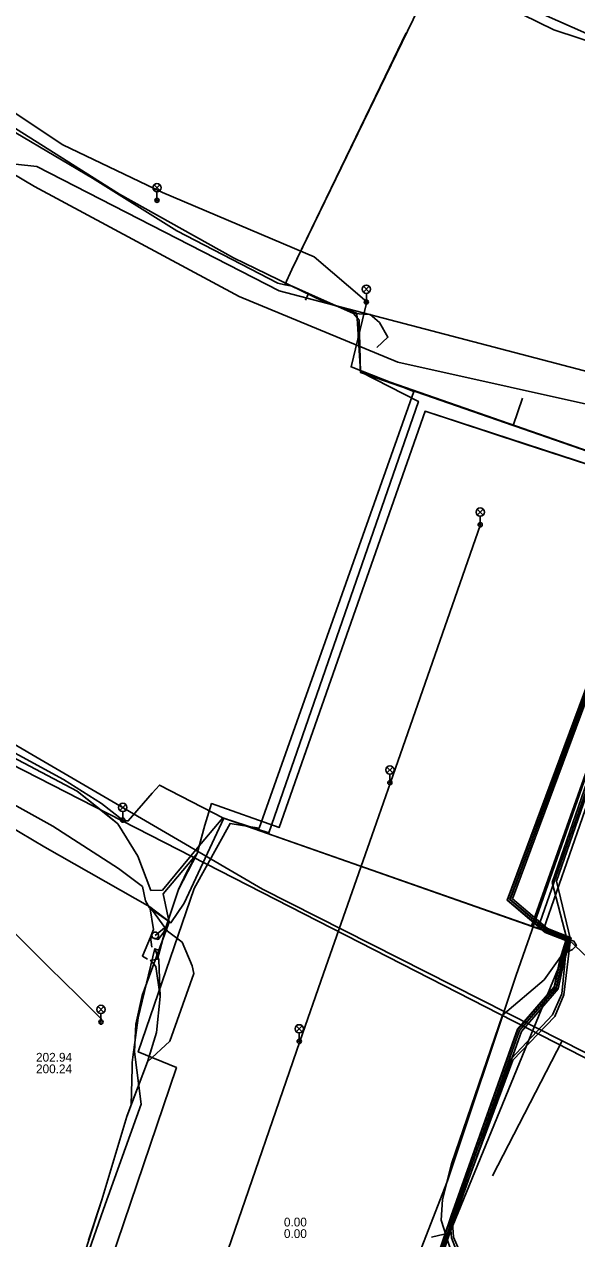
# Model space of a CAD drawing. Extents: x -598932 to -598196, y -1162210 to -1161504.
# Drawn here: x -598603 to -598552.8, y -1162086.4 to -1161976.1 of the extents above; entities that cross this region are included whole.
import ezdxf

# ---------------------------------------------------------------- set-up
doc = ezdxf.new("R2010")
doc.units = 0
for name, color, linetype in [('Vrstva 1', 7, 'Continuous'), ('Vrstva 12', 7, 'Continuous'), ('Vrstva 14', 7, 'Continuous'), ('Vrstva 19', 7, 'Continuous'), ('Vrstva 33', 7, 'Continuous'), ('Vrstva 4', 7, 'Continuous'), ('Vrstva 42', 7, 'Continuous'), ('Vrstva 44', 7, 'Continuous'), ('Vrstva 53', 7, 'Continuous'), ('Vrstva 55', 7, 'Continuous'), ('Vrstva 58', 7, 'Continuous'), ('Vrstva 9', 7, 'Continuous')]:
    doc.layers.add(name, color=color, linetype=linetype)

msp = doc.modelspace()

# ---------------------------------------------------------------- linework, layer by layer
at = {"layer": 'Vrstva 1'}
msp.add_line((-598560.414, -1162080.726), (-598554.112, -1162068.468), dxfattribs=at)
at = {"layer": 'Vrstva 12'}
msp.add_line((-598554.87, -1161976.6), (-598544.19, -1161980.1), dxfattribs=at)
for points in [[(-598627.45, -1161930.97), (-598602.02, -1161951.17), (-598577.74, -1161965.37), (-598554.87, -1161976.6)], [(-598553.63, -1162059.2), (-598555.8, -1162058.35), (-598542.8, -1162021.02), (-598541.73, -1162018.85), (-598539.21, -1162019.28)], [(-598553.63, -1162059.2), (-598553.03, -1162059.41), (-598552.81, -1162059.79), (-598553.17, -1162060.16), (-598554.06, -1162060.58), (-598555.74, -1162062.92), (-598559.51, -1162066.12), (-598564.16, -1162079.63), (-598564.97, -1162082.87), (-598565.09, -1162084.75), (-598563.96, -1162088.26)]]:
    msp.add_lwpolyline(points, dxfattribs=at)
at = {"layer": 'Vrstva 14'}
for points in [[(-598553.423, -1162069.27), (-598647.472, -1162021.146), (-598651.917, -1162018.863), (-598713.299, -1161971.957), (-598714.211, -1161971.254)], [(-598217.743, -1162202.648), (-598218.334, -1162201.688), (-598338.63, -1162114.69), (-598384.62, -1162107.99), (-598422.17, -1162096.1), (-598509.221, -1162075.902), (-598509.921, -1162075.996), (-598510.741, -1162076.086), (-598530.41, -1162081.101), (-598553.423, -1162069.27)]]:
    msp.add_lwpolyline(points, dxfattribs=at)
at = {"layer": 'Vrstva 19'}
msp.add_lwpolyline([(-598526.7, -1162021.32), (-598533.53, -1162012.45), (-598534.5, -1162012.19), (-598579.8, -1162000.3), (-598601.83, -1161989.02), (-598609.34, -1161988.18)], dxfattribs=at)
at = {"layer": 'Vrstva 33'}
for p, q in [((-598591.175, -1161990.675), (-598590.645, -1161991.205)), ((-598591.175, -1161991.205), (-598590.645, -1161990.675)), ((-598590.91, -1161992.09), (-598590.91, -1161991.315)), ((-598572.152, -1161999.9), (-598571.622, -1162000.43)), ((-598572.152, -1162000.43), (-598571.622, -1161999.9)), ((-598571.887, -1162001.315), (-598571.887, -1162000.54)), ((-598561.809, -1162020.152), (-598561.279, -1162020.682)), ((-598561.809, -1162020.682), (-598561.279, -1162020.152)), ((-598561.544, -1162021.567), (-598561.544, -1162020.792)), ((-598570.014, -1162043.577), (-598569.484, -1162044.107)), ((-598570.014, -1162044.107), (-598569.484, -1162043.577)), ((-598569.749, -1162044.992), (-598569.749, -1162044.217)), ((-598594.283, -1162046.988), (-598593.753, -1162047.518)), ((-598594.283, -1162047.518), (-598593.753, -1162046.988)), ((-598594.018, -1162048.403), (-598594.018, -1162047.628)), ((-598596.268, -1162065.34), (-598595.738, -1162065.87)), ((-598596.268, -1162065.87), (-598595.738, -1162065.34)), ((-598596.003, -1162066.755), (-598596.003, -1162065.98)), ((-598578.251, -1162067.1), (-598577.721, -1162067.63)), ((-598578.251, -1162067.63), (-598577.721, -1162067.1)), ((-598577.986, -1162068.515), (-598577.986, -1162067.74))]:
    msp.add_line(p, q, dxfattribs=at)
for centre, radius in [((-598590.91, -1161990.94), 0.375), ((-598590.91, -1161992.09), 0.19), ((-598590.91, -1161992.09), 0.05), ((-598571.887, -1162000.165), 0.375), ((-598571.887, -1162001.315), 0.19), ((-598571.887, -1162001.315), 0.05), ((-598561.544, -1162020.417), 0.375), ((-598561.544, -1162021.567), 0.19), ((-598561.544, -1162021.567), 0.05), ((-598569.749, -1162043.842), 0.375), ((-598569.749, -1162044.992), 0.19), ((-598569.749, -1162044.992), 0.05), ((-598594.018, -1162047.253), 0.375), ((-598594.018, -1162048.403), 0.19), ((-598594.018, -1162048.403), 0.05), ((-598596.003, -1162065.605), 0.375), ((-598596.003, -1162066.755), 0.19), ((-598596.003, -1162066.755), 0.05), ((-598577.986, -1162067.365), 0.375), ((-598577.986, -1162068.515), 0.19), ((-598577.986, -1162068.515), 0.05)]:
    msp.add_circle(centre, radius, dxfattribs=at)
at = {"layer": 'Vrstva 42'}
for p, q in [((-598564.33, -1161968.826), (-598578.662, -1161998.381)), ((-598578.662, -1161998.381), (-598579.286, -1161999.751)), ((-598577.155, -1162000.549), (-598577.42, -1162001.147)), ((-598577.155, -1162000.549), (-598577.42, -1162001.147)), ((-598575.77, -1162001.27), (-598577.155, -1162000.549)), ((-598572.43, -1162007.67), (-598539.14, -1162019.27)), ((-598572.43, -1162007.73), (-598539.14, -1162019.27)), ((-598558.556, -1162012.539), (-598557.7, -1162010.07)), ((-598558.556, -1162012.539), (-598557.7, -1162010.07)), ((-598543.52, -1162020.32), (-598558.28, -1162062.5)), ((-598579.821, -1162049.085), (-598577.366, -1162042.079)), ((-598586.555, -1162048.852), (-598585.946, -1162046.908)), ((-598586.555, -1162048.852), (-598587.25, -1162051.43)), ((-598584.94, -1162048.187), (-598553.644, -1162059.173)), ((-598591.5, -1162059.05), (-598591.39, -1162059.955)), ((-598591.5, -1162059.05), (-598591.39, -1162059.955)), ((-598591.5, -1162059.05), (-598591.39, -1162059.955)), ((-598591.07, -1162058.88), (-598590.08, -1162058.08)), ((-598558.28, -1162062.5), (-598564.52, -1162081.19)), ((-598564.52, -1162081.19), (-598572.6, -1162101.87))]:
    msp.add_line(p, q, dxfattribs=at)
for points in [[(-598696.43, -1161910.03), (-598694.81, -1161909.35), (-598691.6, -1161908.88), (-598690.47, -1161909.23), (-598684.69, -1161915.57), (-598676.56, -1161921.46), (-598666.44, -1161931.11), (-598661.49, -1161936.08), (-598655.62, -1161944.08), (-598644.64, -1161954.28), (-598635.19, -1161962.23), (-598623.88, -1161971.66), (-598615.13, -1161977.53), (-598604.9, -1161984.84), (-598594.32, -1161991.54), (-598583.95, -1161997.32), (-598575.77, -1162001.27), (-598572.76, -1162002.34), (-598572.68, -1162003.32), (-598572.43, -1162007.67)], [(-598616.75, -1161975.23), (-598616.89, -1161975.85), (-598616.35, -1161976.76), (-598613.51, -1161979.33), (-598607.26, -1161983.88), (-598596.76, -1161990.06), (-598589.11, -1161994.85), (-598579.94, -1161999.61), (-598579.286, -1161999.751)], [(-598578.662, -1161998.381), (-598570.182, -1161980.834), (-598568.28, -1161976.86)], [(-598584.94, -1162048.187), (-598587.373, -1162051.113), (-598590.418, -1162054.759), (-598591.461, -1162054.798), (-598592.644, -1162051.677), (-598594.475, -1162048.726), (-598595.514, -1162047.861), (-598598.175, -1162045.777), (-598603.555, -1162042.914), (-598615.772, -1162036.634), (-598619.898, -1162034.24), (-598623.918, -1162031.949), (-598625.034, -1162030.4), (-598630.842, -1162026.844), (-598645.114, -1162018.576), (-598650.929, -1162014.808), (-598655.57, -1162011.409), (-598660.099, -1162008.595), (-598670.573, -1162001.081), (-598684.323, -1161990.333), (-598691.62, -1161985.078), (-598695, -1161981.986), (-598698.099, -1161980.56)], [(-598577.42, -1162001.147), (-598577.155, -1162000.549), (-598578.64, -1161999.89), (-598579.286, -1161999.751), (-598578.662, -1161998.381)], [(-598577.155, -1162000.549), (-598578.64, -1161999.89), (-598579.286, -1161999.751)], [(-598573.05, -1162002.37), (-598577.155, -1162000.549), (-598577.42, -1162001.147)], [(-598577.155, -1162000.549), (-598573.05, -1162002.37), (-598572.53, -1162002.96), (-598572.43, -1162007.73), (-598539.14, -1162019.27)], [(-598558.556, -1162012.539), (-598572.43, -1162007.73), (-598572.53, -1162002.96), (-598573.05, -1162002.37), (-598577.155, -1162000.549)], [(-598575.77, -1162001.27), (-598572.76, -1162002.34), (-598572.68, -1162003.32), (-598572.43, -1162007.67)], [(-598573.05, -1162002.37), (-598571.55, -1162002.45), (-598570.7, -1162003.2), (-598569.93, -1162004.52), (-598570.95, -1162005.46)], [(-598573.05, -1162002.37), (-598572.53, -1162002.96), (-598572.43, -1162007.73)], [(-598584.87, -1162048.23), (-598580.734, -1162049.565), (-598567.159, -1162010.365), (-598572.43, -1162007.67)], [(-598536.03, -1162015.6), (-598537.275, -1162019.398), (-598537.651, -1162020.546), (-598543.652, -1162018.729), (-598566.56, -1162011.25), (-598579.821, -1162049.085), (-598585.946, -1162046.908), (-598586.555, -1162048.852), (-598587.25, -1162051.43)], [(-598585.946, -1162046.908), (-598579.821, -1162049.085), (-598566.56, -1162011.25)], [(-598543.652, -1162018.729), (-598557.537, -1162014.21), (-598566.56, -1162011.25)], [(-598556.872, -1162058.04), (-598542.722, -1162018.069), (-598539.213, -1162019.268)], [(-598649.502, -1162032.103), (-598647.624, -1162032.536), (-598646.31, -1162031.88), (-598643.86, -1162030.02), (-598641.2, -1162029.6), (-598639.24, -1162031.15), (-598635.67, -1162035), (-598627.11, -1162038.48), (-598619.07, -1162041.79), (-598615.71, -1162042.56), (-598614.58, -1162042.86), (-598601.101, -1162050.854), (-598591.558, -1162056.282), (-598591.22, -1162058.33), (-598591.5, -1162059.05), (-598592.24, -1162060.76), (-598591.784, -1162061.026)], [(-598649.502, -1162032.103), (-598647.624, -1162032.536), (-598646.31, -1162031.88), (-598643.86, -1162030.02), (-598641.2, -1162029.6), (-598639.24, -1162031.15), (-598635.67, -1162035), (-598627.11, -1162038.48), (-598619.07, -1162041.79), (-598615.71, -1162042.56), (-598614.58, -1162042.86), (-598601.101, -1162050.854), (-598591.558, -1162056.282), (-598591.22, -1162058.33), (-598591.5, -1162059.05), (-598592.24, -1162060.76), (-598591.784, -1162061.026)], [(-598594.09, -1162048.46), (-598593.52, -1162048.47), (-598591.34, -1162045.96), (-598590.68, -1162045.22), (-598584.86, -1162048.24)], [(-598590.08, -1162058.08), (-598588.96, -1162054.71), (-598587.25, -1162051.43), (-598586.555, -1162048.852), (-598585.946, -1162046.908), (-598579.821, -1162049.085)], [(-598587.25, -1162051.43), (-598590.34, -1162055.11), (-598589.81, -1162057.67), (-598592.26, -1162064.33), (-598592.83, -1162066.93), (-598592.96, -1162069.47), (-598592.36, -1162074.22), (-598595.78, -1162083.76), (-598600.67, -1162097.79), (-598605.47, -1162112.02), (-598610.59, -1162125.88), (-598615.71, -1162139.45), (-598620.8, -1162152.27), (-598625.98, -1162166.85), (-598630.7, -1162180.39), (-598633.77, -1162187.31)], [(-598591.52, -1162061.172), (-598590.87, -1162061.04), (-598590.08, -1162058.08), (-598588.96, -1162054.71), (-598588.2, -1162053.11), (-598587.25, -1162051.43)], [(-598590.28, -1162058.58), (-598590.08, -1162058.08), (-598588.96, -1162054.71)], [(-598591.77, -1162070.37), (-598589.74, -1162068.49), (-598587.55, -1162062.34), (-598587.72, -1162061.63), (-598588.63, -1162059.48), (-598589.95, -1162058.5), (-598591.558, -1162056.282)], [(-598591.77, -1162070.37), (-598589.74, -1162068.49), (-598587.55, -1162062.34), (-598587.72, -1162061.63), (-598588.63, -1162059.48), (-598589.95, -1162058.5), (-598591.558, -1162056.282)], [(-598588.43, -1162055.94), (-598589.65, -1162057.73), (-598591.558, -1162056.282)], [(-598588.43, -1162055.94), (-598589.65, -1162057.73), (-598591.558, -1162056.282)], [(-598591.5, -1162059.05), (-598590.79, -1162059.24), (-598590.28, -1162058.58)], [(-598591.5, -1162059.05), (-598590.79, -1162059.24), (-598590.28, -1162058.58)], [(-598591.5, -1162059.05), (-598590.79, -1162059.24), (-598590.28, -1162058.58)], [(-598590.77, -1162058.88), (-598590.771, -1162058.854), (-598590.775, -1162058.828), (-598590.78, -1162058.802), (-598590.788, -1162058.777), (-598590.798, -1162058.753), (-598590.81, -1162058.73), (-598590.824, -1162058.708), (-598590.84, -1162058.687), (-598590.858, -1162058.668), (-598590.877, -1162058.65), (-598590.898, -1162058.634), (-598590.92, -1162058.62), (-598590.943, -1162058.608), (-598590.967, -1162058.598), (-598590.992, -1162058.59), (-598591.018, -1162058.585), (-598591.044, -1162058.581), (-598591.07, -1162058.58), (-598591.096, -1162058.581), (-598591.122, -1162058.585), (-598591.148, -1162058.59), (-598591.173, -1162058.598), (-598591.197, -1162058.608), (-598591.22, -1162058.62), (-598591.242, -1162058.634), (-598591.263, -1162058.65), (-598591.282, -1162058.668), (-598591.3, -1162058.687), (-598591.316, -1162058.708), (-598591.33, -1162058.73), (-598591.342, -1162058.753), (-598591.352, -1162058.777), (-598591.36, -1162058.802), (-598591.365, -1162058.828), (-598591.369, -1162058.854), (-598591.37, -1162058.88), (-598591.369, -1162058.906), (-598591.365, -1162058.932), (-598591.36, -1162058.958), (-598591.352, -1162058.983), (-598591.342, -1162059.007), (-598591.33, -1162059.03), (-598591.316, -1162059.052), (-598591.3, -1162059.073), (-598591.282, -1162059.092), (-598591.263, -1162059.11), (-598591.242, -1162059.126), (-598591.22, -1162059.14), (-598591.197, -1162059.152), (-598591.173, -1162059.162), (-598591.148, -1162059.17), (-598591.122, -1162059.175), (-598591.096, -1162059.179), (-598591.07, -1162059.18), (-598591.044, -1162059.179), (-598591.018, -1162059.175), (-598590.992, -1162059.17), (-598590.967, -1162059.162), (-598590.943, -1162059.152), (-598590.92, -1162059.14), (-598590.898, -1162059.126), (-598590.877, -1162059.11), (-598590.858, -1162059.092), (-598590.84, -1162059.073), (-598590.824, -1162059.052), (-598590.81, -1162059.03), (-598590.798, -1162059.007), (-598590.788, -1162058.983), (-598590.78, -1162058.958), (-598590.775, -1162058.932), (-598590.771, -1162058.906), (-598590.77, -1162058.88)], [(-598590.08, -1162058.08), (-598590.662, -1162060.262), (-598591.121, -1162060.095)], [(-598600.08, -1162095.77), (-598595.92, -1162082.91), (-598593.66, -1162075.33), (-598593.25, -1162074.28), (-598593.18, -1162070.92), (-598593.17, -1162070.42), (-598593.1, -1162069.93), (-598592.61, -1162066.37), (-598591.11, -1162060.06)], [(-598590.61, -1162064.44), (-598590.74, -1162061.11), (-598591.107, -1162060.058)], [(-598590.61, -1162064.44), (-598590.74, -1162061.11), (-598591.107, -1162060.058)], [(-598553.48, -1162059.19), (-598554.19, -1162061.22), (-598564.31, -1162085.91), (-598565.96, -1162086.3)], [(-598591.505, -1162061.135), (-598591, -1162061.71), (-598590.61, -1162064.44), (-598590.95, -1162067.69), (-598591.77, -1162070.37), (-598593.66, -1162075.33)], [(-598591.505, -1162061.135), (-598591, -1162061.71), (-598590.61, -1162064.44), (-598590.95, -1162067.69), (-598591.77, -1162070.37), (-598593.25, -1162074.28)], [(-598597.12, -1162086.56), (-598595.92, -1162082.91), (-598593.66, -1162075.33), (-598593.25, -1162074.28), (-598593.18, -1162070.92), (-598593.17, -1162070.42)]]:
    msp.add_lwpolyline(points, dxfattribs=at)
at = {"layer": 'Vrstva 44'}
for points in [[(-598569.304, -1162099.577), (-598564.154, -1162084.367), (-598558.138, -1162067.429), (-598554.801, -1162063.572), (-598554.247, -1162061.114), (-598553.68, -1162059.292), (-598555.611, -1162058.557), (-598559.058, -1162055.671), (-598544.689, -1162017.151)], [(-598569.116, -1162099.643), (-598564.248, -1162085.266), (-598563.966, -1162084.433), (-598561.75, -1162078.194), (-598557.962, -1162067.531), (-598554.619, -1162063.668), (-598554.053, -1162061.166), (-598553.742, -1162060.151), (-598553.44, -1162059.168), (-598553.707, -1162059.067), (-598555.509, -1162058.383), (-598558.822, -1162055.609), (-598544.571, -1162017.409)], [(-598554.143, -1162064.182), (-598553.742, -1162060.151), (-598553.654, -1162059.27), (-598553.707, -1162059.067), (-598555.02, -1162054.064), (-598543.881, -1162022.003)], [(-598543.59, -1162022.251), (-598554.609, -1162053.954), (-598553.356, -1162059.245), (-598553.94, -1162064.291)], [(-598563.332, -1162088.466), (-598564.168, -1162086.347), (-598564.248, -1162085.266), (-598564.27, -1162084.971), (-598561.75, -1162078.194), (-598558.739, -1162070.098), (-598554.966, -1162066.097), (-598554.143, -1162064.182)], [(-598553.94, -1162064.291), (-598554.78, -1162066.24), (-598558.57, -1162070.23), (-598564.07, -1162085.01), (-598563.98, -1162086.31), (-598563.067, -1162088.389)]]:
    msp.add_lwpolyline(points, dxfattribs=at)
at = {"layer": 'Vrstva 53'}
msp.add_line((-598553.59, -1162059.2), (-598556.32, -1162058.24), dxfattribs=at)
for points in [[(-598468.08, -1161988.79), (-598479.18, -1162021.74), (-598479.69, -1162022.33), (-598482.39, -1162022.35), (-598487.98, -1162021.57), (-598505.68, -1162017.91), (-598511.36, -1162016.46), (-598513.72, -1162016.38), (-598514.8, -1162016.28), (-598521.05, -1162015.98), (-598526.93, -1162015.25), (-598528.15, -1162015.65), (-598529.25, -1162016.53), (-598532.03, -1162021.35), (-598533.21, -1162021.76), (-598535.05, -1162021.65), (-598539.21, -1162019.43), (-598541.87, -1162018.23), (-598543.21, -1162020.83), (-598556.32, -1162058.24)], [(-598591.6, -1162056.38), (-598591.95, -1162055.74), (-598592.23, -1162054.45), (-598594.42, -1162052.8), (-598600.38, -1162048.96), (-598603.64, -1162047.13), (-598611.48, -1162042.8), (-598623.43, -1162035.99), (-598632.06, -1162031.49), (-598634.31, -1162030.66), (-598644.06, -1162025.96), (-598645.14, -1162025.4), (-598646.52, -1162024.69), (-598657.07, -1162020.06), (-598661.29, -1162018), (-598662.7, -1162017.52), (-598663.12, -1162018.01), (-598665, -1162020.27)], [(-598556.32, -1162058.24), (-598584.85, -1162048.24), (-598588.43, -1162055.94)], [(-598591.6, -1162056.38), (-598589.65, -1162057.73), (-598588.43, -1162055.94)], [(-598553.59, -1162059.2), (-598549.26, -1162063.31), (-598542.72, -1162072.74), (-598540.79, -1162073.5)]]:
    msp.add_lwpolyline(points, dxfattribs=at)
at = {"layer": 'Vrstva 55'}
for points in [[(-598538.426, -1162013.595), (-598569.03, -1162006.79), (-598583.43, -1162000.81), (-598602.04, -1161990.84), (-598617.15, -1161981.87), (-598630.44, -1161972.68), (-598653.03, -1161953.63), (-598683.76, -1161922.51), (-598678.33, -1161917.53), (-598684.31, -1161911.55), (-598687.3, -1161909.33), (-598691.29, -1161908.33), (-598694.72, -1161908.89), (-598697.83, -1161910.55), (-598701.59, -1161914.87), (-598725.38, -1161945.83), (-598731.11, -1161953.74), (-598726.48, -1161957.43), (-598725.72, -1161956.78), (-598724.89, -1161957.11), (-598720.519, -1161951.972)], [(-598635.847, -1162206.96), (-598629.97, -1162189.7), (-598621.09, -1162162.42), (-598598.1, -1162097.33), (-598589.15, -1162070.89), (-598592.61, -1162069.46), (-598587.52, -1162054.61), (-598584.27, -1162048.71), (-598581.62, -1162049.12), (-598567.59, -1162009.46), (-598573.28, -1162007.22), (-598571.851, -1162001.315), (-598576.64, -1161997.21), (-598590.4, -1161991.37), (-598599.45, -1161987.03), (-598615.67, -1161976.28), (-598632.44, -1161961.96), (-598678.26, -1161917.47), (-598684.987, -1161911.745), (-598688.029, -1161910.224), (-598691.806, -1161909.122), (-598694.533, -1161909.122), (-598697.86, -1161910.3), (-598707.4, -1161922.62)], [(-598587.64, -1162096.67), (-598587.271, -1162095.598), (-598584.453, -1162087.419), (-598577.94, -1162068.51), (-598575.783, -1162062.349), (-598571.189, -1162049.225), (-598569.71, -1162045), (-598563.847, -1162028.227), (-598561.51, -1162021.54)], [(-598607.868, -1162040.118), (-598599.4, -1162044.712), (-598595.954, -1162046.881), (-598594.018, -1162048.403)], [(-598603.742, -1162058.78), (-598600.7, -1162061.781), (-598598.099, -1162064.349), (-598595.97, -1162066.449), (-598595.999, -1162066.738)]]:
    msp.add_lwpolyline(points, dxfattribs=at)
at = {"layer": 'Vrstva 58'}
for p in [(-598584.94, -1162048.187), (-598553.644, -1162059.173)]:
    msp.add_line(p, (-598556.872, -1162058.04), dxfattribs=at)
for points in [[(-598468.847, -1161997.004), (-598474.74, -1161995.919), (-598475.488, -1161995.781), (-598478.287, -1161995.178), (-598494.053, -1161991.976), (-598541.472, -1161981.52), (-598578.948, -1161964.943), (-598630.191, -1161928.985), (-598655.175, -1161905.777), (-598662.179, -1161910.88), (-598682.84, -1161933.505), (-598697.858, -1161918.482), (-598699.937, -1161917.16), (-598721.671, -1161944.79), (-598806.154, -1162058.425), (-598849.895, -1162115.36), (-598896.973, -1162178.006), (-598919.37, -1162206.96)], [(-598703.395, -1161978.841), (-598699.591, -1161979.981), (-598698.099, -1161980.56), (-598695, -1161981.986), (-598691.62, -1161985.078), (-598684.323, -1161990.333), (-598670.573, -1162001.081), (-598660.099, -1162008.595), (-598655.57, -1162011.409), (-598650.929, -1162014.808), (-598645.114, -1162018.576), (-598630.842, -1162026.844), (-598625.034, -1162030.4), (-598623.918, -1162031.949), (-598619.898, -1162034.24), (-598615.772, -1162036.634), (-598603.555, -1162042.914), (-598598.175, -1162045.777), (-598594.475, -1162048.726), (-598592.644, -1162051.677), (-598591.461, -1162054.798), (-598590.418, -1162054.759), (-598587.373, -1162051.113), (-598584.94, -1162048.187)], [(-598536.03, -1162015.6), (-598537.275, -1162019.398), (-598537.651, -1162020.546), (-598543.652, -1162018.729), (-598566.56, -1162011.25), (-598579.821, -1162049.085), (-598585.946, -1162046.908), (-598586.555, -1162048.852), (-598587.25, -1162051.43)], [(-598536.03, -1162015.6), (-598537.275, -1162019.398), (-598537.651, -1162020.546), (-598543.652, -1162018.729), (-598566.56, -1162011.25), (-598579.821, -1162049.085), (-598585.946, -1162046.908), (-598586.555, -1162048.852), (-598587.25, -1162051.43)], [(-598485.428, -1162023.212), (-598491.232, -1162022.044), (-598501.111, -1162020.174), (-598502.849, -1162019.814), (-598514.314, -1162017.439), (-598515.375, -1162017.491), (-598518.791, -1162018.178), (-598520.498, -1162018.937), (-598525.141, -1162019.701), (-598528.851, -1162017.497), (-598529.806, -1162017.554), (-598532.141, -1162019.44), (-598533.094, -1162020.113), (-598537.405, -1162019.662), (-598539.175, -1162019.396), (-598544.735, -1162017.044), (-598559.096, -1162055.682), (-598555.634, -1162058.614), (-598553.774, -1162059.339), (-598554.304, -1162061.11), (-598554.825, -1162063.558), (-598558.146, -1162067.408), (-598564.189, -1162084.364), (-598569.319, -1162099.564)], [(-598485.428, -1162023.212), (-598491.232, -1162022.044), (-598501.111, -1162020.174), (-598502.849, -1162019.814), (-598514.314, -1162017.439), (-598515.375, -1162017.491), (-598518.791, -1162018.178), (-598520.498, -1162018.937), (-598525.141, -1162019.701), (-598528.851, -1162017.497), (-598529.806, -1162017.554), (-598532.141, -1162019.44), (-598533.094, -1162020.113), (-598537.405, -1162019.662), (-598539.175, -1162019.396), (-598544.735, -1162017.044), (-598559.096, -1162055.682), (-598555.634, -1162058.614), (-598553.774, -1162059.339), (-598554.304, -1162061.11), (-598554.825, -1162063.558), (-598558.146, -1162067.408), (-598564.189, -1162084.364), (-598569.319, -1162099.564)], [(-598544.62, -1162017.31), (-598558.86, -1162055.62), (-598555.53, -1162058.44), (-598553.53, -1162059.22), (-598554.11, -1162061.16), (-598554.64, -1162063.65), (-598557.97, -1162067.51), (-598564, -1162084.43), (-598569.13, -1162099.63)], [(-598544.62, -1162017.31), (-598558.86, -1162055.62), (-598555.53, -1162058.44), (-598553.53, -1162059.22), (-598554.11, -1162061.16), (-598554.64, -1162063.65), (-598557.97, -1162067.51), (-598564, -1162084.43), (-598569.13, -1162099.63)], [(-598544.505, -1162017.576), (-598558.624, -1162055.558), (-598555.426, -1162058.266), (-598553.286, -1162059.101), (-598553.916, -1162061.21), (-598554.455, -1162063.742), (-598557.794, -1162067.612), (-598563.811, -1162084.496), (-598568.941, -1162099.696)], [(-598556.872, -1162058.04), (-598542.722, -1162018.069), (-598539.213, -1162019.268)], [(-598591.52, -1162061.172), (-598590.87, -1162061.04), (-598590.08, -1162058.08), (-598588.96, -1162054.71), (-598588.2, -1162053.11), (-598587.25, -1162051.43)], [(-598587.25, -1162051.43), (-598588.2, -1162053.11), (-598588.96, -1162054.71), (-598590.08, -1162058.08), (-598590.87, -1162061.04), (-598591.52, -1162061.172)]]:
    msp.add_lwpolyline(points, dxfattribs=at)
at = {"layer": 'Vrstva 9'}
for points in [[(-598653.484, -1162013.336), (-598652.475, -1162014.059), (-598625.289, -1162029.029), (-598589.053, -1162050.166), (-598581.324, -1162054.674)], [(-598581.324, -1162054.674), (-598554.112, -1162068.468), (-598537.958, -1162076.656), (-598505.417, -1162093.152)]]:
    msp.add_lwpolyline(points, dxfattribs=at)

# ---------------------------------------------------------------- texts
at = {"layer": 'Vrstva 12'}
for s, p in [('202.94', (-598601.899, -1162070.354)), ('200.24', (-598601.899, -1162071.404))]:
    msp.add_text(s, height=0.8, dxfattribs=at).set_placement(p)
at = {"layer": 'Vrstva 4'}
for p in [(-598579.377, -1162085.326), (-598579.377, -1162086.376)]:
    msp.add_text('0.00', height=0.8, dxfattribs=at).set_placement(p)

doc.saveas('drawing.dxf')
